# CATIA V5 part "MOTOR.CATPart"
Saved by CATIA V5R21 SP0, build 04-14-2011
Part number: MOTOR
Bounding box of the stored display mesh (mm): x -13.49 to 20.5, y -34.25 to 48.25, z -17 to 13.5
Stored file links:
  D:\MENA 3D\BISMARK\MOTOR.CATPart
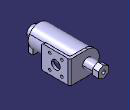
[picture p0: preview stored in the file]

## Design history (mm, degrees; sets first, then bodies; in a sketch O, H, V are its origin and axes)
Body1 (main body)
  Set1
    Sketch1 on xy-plane, origin (0, 0, 0), H (1, 0, 0), V (0, 1, 0)
      line L1 (12.5, 26.75) -> (12.5, -26.75)
      line L2 (12.5, -26.75) -> (0, -26.75)
      line L3 (0, 26.75) -> (12.5, 26.75)
      point P1 (12.5, 26.75)
      point P3 (-12.5, -26.75)
      point P4 (-12.5, 26.75)
      line L4 (0, 26.75) -> (0, -26.75)
      length L1 = 53.5
      distance P4 P1 = 25
      vertical: L1 V, L4 V
      horizontal: L2 H, L3 H
      equidistance: L2 L3 O
  Shaft1: profile Sketch1, axis Sketch1.L4, angle 360
  Sketch2 on face of Shaft1 from Sketch1.L2, origin (0, -26.75, 0), H (1, 0, 0), V (0, 0, 1)
    circle A1 centre (0, 0) radius 6.75
    radius A1 = 6.75
  Pad1: profile Sketch2, direction (0, -1, 0), length 7.5
  Sketch3 on face of Shaft1 from Sketch1.L2, origin (0, -26.75, 0), H (1, 0, 0), V (0, 0, 1)
    point P1 (0, -13)
    line L1 (7, -9) -> (7, -17)
    line L2 (7, -17) -> (-7, -17)
    line L3 (-7, -17) -> (-7, -9)
    line L4 (-7, -9) -> (7, -9)
    distance L3 L1 = 14
    distance L4 L2 = 8
    distance H L2 = 17
    coincidence: P1 V
    vertical: L1 V, L3 V
    horizontal: L2 H, L4 H
    equidistance: L1 L3 P1, L2 L4 P1
  Pad2: profile Sketch3, direction (0, -1, 0), length 5
  Sketch4 on face of Shaft1 from Sketch1.L3, origin (0, 26.75, 0), H (-1, 0, 0), V (0, 0, 1)
    circle A1 centre (0, 0) radius 5.5
    radius A1 = 5.5
  Pad3: profile Sketch4, direction (0, 1, 0), length 15
  Sketch5 on end face of Pad3, origin (0, 41.75, 0), H (-1, 0, 0), V (0, 0, 1)
    point P1 (5.958, 3.5359)
    point P2 (-0.0831, 6.9277)
    point P3 (-6.0411, 3.3919)
    point P4 (-5.958, -3.5359)
    point P5 (0.0831, -6.9277)
    point P6 (6.0411, -3.3919)
    point P7 (2.9374, 5.2318)
    line L1 (5.958, 3.5359) -> (-0.0831, 6.9277)
    line L2 (-0.0831, 6.9277) -> (-6.0411, 3.3919)
    line L3 (-6.0411, 3.3919) -> (-5.958, -3.5359)
    line L4 (-5.958, -3.5359) -> (0.0831, -6.9277)
    line L5 (0.0831, -6.9277) -> (6.0411, -3.3919)
    line L6 (6.0411, -3.3919) -> (5.958, 3.5359)
    construction line L7 (0, 0) -> (2.9374, 5.2318)
    construction circle A1 centre (0, 0) radius 6.9282
    construction arc A2 centre (0.0831, -6.9277) radius 6.9282 from (-5.958, -3.5359) to (6.0411, -3.3919) cw
    construction arc A3 centre (-0.0831, 6.9277) radius 6.9282 from (-6.0411, 3.3919) to (5.958, 3.5359) ccw
    distance L6 L3 = 12
    coincidence: A1 P1, A1 P2, A1 P3, A1 P4, A1 P5, A1 P6, A2 O, A3 O
    midpoint: P7 L1
    parallelism: L1 L4
  Pad4: profile Sketch5, direction (0, 1, 0), length 6.5
  Sketch6 on end face of Pad4, origin (-0.1828, 48.25, -0.1026), H (1, 0, 0), V (0, 0, -1)
    point P1 (0, 0)
  Hole1: placed by Sketch6, at (-0.1828, 48.25, -0.1026) direction (0, -1, 0), diameter 4, depth 22
  Sketch7 on face of Shaft1 from Sketch1.L3, origin (0, 26.75, 0), H (-1, 0, 0), V (0, 0, 1)
    arc A1 centre (0, 0) radius 13.5 from (0, -13.5) to (0, 13.5) ccw
    point P1 (0, 13.5)
    line L1 (0, 13.5) -> (-20.5, 13.5)
    line L2 (-20.5, 13.5) -> (-20.5, -13.5)
    point P3 (-20.5, -13.5)
    point P4 (0, -13.5)
    line L3 (0, -13.5) -> (-20.5, -13.5)
    point P5 (-20.5, -13.5)
    radius A1 = 13.5
    distance L2 A1 = 34
    coincidence: P1 V, P4 V, P5 L2, P3 P5
    tangency: L1 A1, L3 A1
    vertical: L2 V
    horizontal: L3 H, L1 H
  Pad5: profile Sketch7, direction (0, 1, 0), length 3
  Sketch8 on face of Pad5 from Sketch7.L2, origin (20.5, 0, 0), H (0, 1, 0), V (0, 0, 1)
    point P1 (13.25, 0)
    line L1 (29.75, 13.5) -> (29.75, -13.5)
    line L2 (29.75, -13.5) -> (-3.25, -13.5)
    line L3 (-3.25, -13.5) -> (-3.25, 13.5)
    line L4 (-3.25, 13.5) -> (29.75, 13.5)
    reference projected line E1 (29.75, 13.5) -> (29.75, -13.5) from edge [face of Pad5 from Sketch7.L2 | end face of Pad5]
    reference projected line E2 (26.75, 13.5) -> (29.75, 13.5) from edge [face of Pad5 from Sketch7.L2 | face of Pad5 from Sketch7.L1]
    circle A1 centre (13.25, 0) radius 5
    circle A2 centre (6.25, 8.5) radius 1.5
    point P6 (6.25, 8.5)
    circle A3 centre (20.25, 8.5) radius 1.5
    point P7 (20.25, 8.5)
    construction line L5 (13.25, 17.6181) -> (13.25, -22.1596)
    circle A4 centre (6.25, -8.5) radius 1.5
    circle A5 centre (20.25, -8.5) radius 1.5
    distance L1 L3 = 33
    radius A1 = 5
    radius A3 = 1.5
    radius A2 = 1.5
    distance P6 P7 = 14
    distance L4 P7 = 5
    coincidence: P1 H, L1 E1, L4 E2, L5 P1
    vertical: L1 V, L3 V, L5 V
    horizontal: L2 H, L4 H
    equidistance: L1 L3 P1, L2 L4 P1
    symmetry: P7 P6 L5, A2 A4 H, A3 A5 H
  Pad6: profile Sketch8, direction (-1, 0, 0), length 3
  Fillet1: radius 2, on edge [face of Pad6 | face of Pad6]; edge [start face of Pad5 | end face of Pad6]; edge [face of Pad6 | face of Pad6 from Sketch8.L3]; edge [face of Pad6 from Sketch8.L3 | face of Pad6]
